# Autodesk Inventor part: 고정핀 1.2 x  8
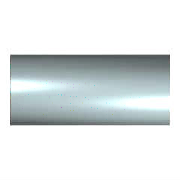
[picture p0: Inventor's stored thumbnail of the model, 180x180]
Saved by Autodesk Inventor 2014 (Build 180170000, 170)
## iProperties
IsCustomPart: 1
Created: 2012-02
Part Number: 고정핀 1.2 x  8
Material: 강철, 연강
Description: 평행 핀
Document SubType Name: Modeling
Standard: KS B 1320
Designer: P15F
Standards Organization: KS
Language: ko-KR
Size Designation: C 1.2 x  8
Categories: <MemberInstance><Categories><Category DisplayName="조임쇠" InternalName="e4da775c-781d-43d5-af7c-5136215cf5a6" Mnemonic="FSTN"><Category DisplayName="핀" InternalNa
Density: 1 g/cm^3
Appearance: Yellow
Author: P15F
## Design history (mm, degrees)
sketch "스케치1"
  geometry: C1 r 0.6 at (0, 0); 1 further point
  constraints: 1 centre point, 1 coincident
  dimensions: "d1" = 1.2 diameter of C1 (= NND)
extrude "본체" new body sketch "스케치1" distance "d2" = 8 (= NLG); taper "d3" = 0 deg
node "작업 평면1"
body "Solid1"
other parameters: "NND" = 1.2 [user parameter; used in 1 equation term], "NLG" = 8 [user parameter; used in 1 equation term], "d8" = 0, "d9" = 0, "d10" = 0
